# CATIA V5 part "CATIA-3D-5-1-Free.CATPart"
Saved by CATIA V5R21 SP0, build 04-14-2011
Part number: CATIA-3D-5-1-Free
Bounding box of the stored display mesh (mm): x -44 to 44, y -32 to 32, z 0 to 75
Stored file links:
  C:\Users\Rasoul Mohammadi\Desktop\CATIA-Free\3D\CATIA-3D-5-1-Free.CATPart
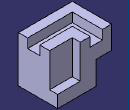
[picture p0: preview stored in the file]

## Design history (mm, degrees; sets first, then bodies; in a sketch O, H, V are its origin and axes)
Body1 (main body)
  Sketch1 on xy-plane, origin (0, 0, 0), H (1, 0, 0), V (0, 1, 0)
    line L1 (44, 32) -> (44, -32)
    line L2 (44, -32) -> (-44, -32)
    line L3 (-44, -32) -> (-44, 32)
    line L4 (-44, 32) -> (44, 32)
    length L4 = 88
    length L1 = 64
    vertical: L1 V, L3 V
    horizontal: L2 H, L4 H
    equidistance: L1 L3 O, L2 L4 O
  Pad1: profile Sketch1, direction (0, 0, 1), length 75
  Sketch2 on face of Pad1 from Sketch1.L4, origin (0, 32, 0), H (-1, 0, 0), V (0, 0, 1)
    line L1 (-44, 75) -> (-7, 75)
    line L2 (-7, 75) -> (-7, 20)
    line L3 (-7, 20) -> (-44, 20)
    line L4 (-44, 20) -> (-44, 75)
    reference projected line E1 (-44, 75) -> (44, 75) from edge [face of Pad1 from Sketch1.L4 | end face of Pad1]
    reference projected line E2 (-44, 0) -> (-44, 75) from edge [face of Pad1 from Sketch1.L4 | face of Pad1 from Sketch1.L1]
    length L2 = 55
    length L1 = 37
    horizontal: L1 H, L3 H
    vertical: L2 V, L4 V
    coincidence: E1 L1, E2 L4
  Pocket1: profile Sketch2, direction (0, -1, 0), length 13
  Sketch3 on end face of Pad1, origin (0, 0, 75), H (1, 0, 0), V (0, 1, 0)
    projected line E1 (44, -32) -> (44, 19) from edge [face of Pad1 from Sketch1.L1 | end face of Pad1]
    projected line E2 (44, -17) -> (44, 3) from edge [face of Pad1 from Sketch1.L1 | end face of Pad1]
    projected line E3 (7, 32) -> (-44, 32) from edge [face of Pad1 from Sketch1.L4 | end face of Pad1]
    line L1 (44, 3) -> (-9, 3)
    line L2 (-9, 3) -> (-9, 32)
    point P6 (-9, 32)
    line L3 (-9, 32) -> (-29, 32)
    point P7 (-29, 32)
    line L4 (-29, 32) -> (-29, -17)
    line L5 (-29, -17) -> (44, -17)
    reference projected line E4 (-44, -32) -> (44, -32) from edge [face of Pad1 from Sketch1.L2 | end face of Pad1]
    reference projected line E5 (-44, -32) -> (44, -32) from edge [face of Pad1 from Sketch1.L2 | end face of Pad1]
    reference projected line E6 (44, 32) -> (44, 19) from edge [face of Pocket1 from Sketch2.L3 | face of Pad1 from Sketch1.L1]
    point P9 (-9, 32)
    point P10 (-29, 32)
    distance L5 E4 = 15
    distance L1 E5 = 35
    distance E6 L2 = 53
    distance L2 L4 = 20
    horizontal: L1 H, L3 H, L5 H
    coincidence: P6 E3, P6 L2, P7 L4, P6 P9, P7 P10
    vertical: L2 V, L4 V
  Pocket2: profile Sketch3, direction (0, 0, -1), length 15
  Sketch4 on face of Pad1 from Sketch1.L3, origin (-44, 0, 0), H (0, -1, 0), V (0, 0, 1)
    line L1 (-32, 0) -> (16, 0)
    line L2 (16, 0) -> (16, 38)
    line L3 (16, 38) -> (-32, 38)
    line L4 (-32, 38) -> (-32, 0)
    reference projected line E1 (-32, 0) -> (32, 0) from edge [start face of Pad1 | face of Pad1 from Sketch1.L3]
    reference projected line E2 (-32, 0) -> (-32, 75) from edge [face of Pad1 from Sketch1.L3 | face of Pad1 from Sketch1.L4]
    length L3 = 48
    length L2 = 38
    horizontal: L1 H, L3 H
    vertical: L2 V, L4 V
    coincidence: L1 E1, L4 E2
  Pocket3: profile Sketch4, direction (1, 0, 0), length 25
